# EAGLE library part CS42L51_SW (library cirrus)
CODEC (Software Mode) Low Power, Stereo CODEC with Headphone Amp
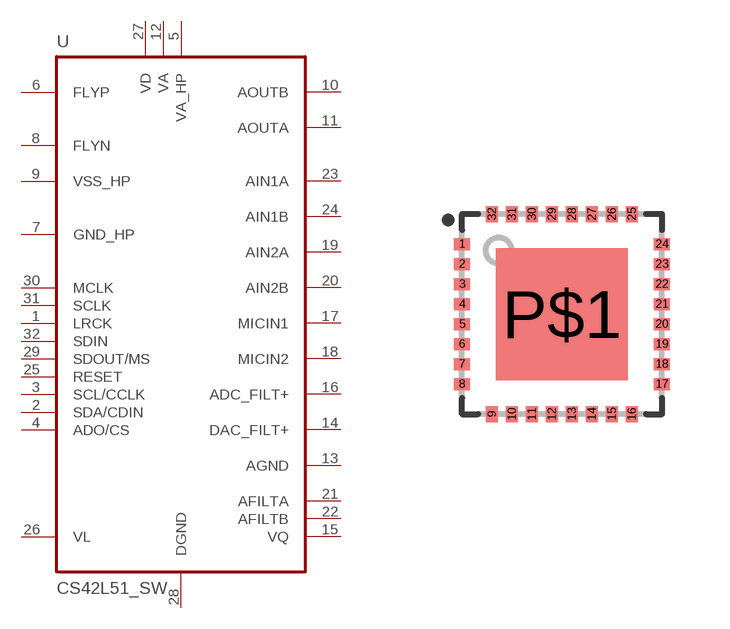
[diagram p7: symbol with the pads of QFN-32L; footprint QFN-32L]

Designator prefix U

## CS42L51_SW  [QFN-32L]
1  LRCK
2  SDA/CDIN
3  SCL/CCLK
4  ADO/CS
5  VA_HP
6  FLYP
7  GND_HP
8  FLYN
9  VSS_HP
10  AOUTB
11  AOUTA
12  VA
13  AGND
14  DAC_FILT+
15  VQ
16  ADC_FILT+
17  MICIN1
18  MICIN2
19  AIN2A
20  AIN2B
21  AFILTA
22  AFILTB
23  AIN1A
24  AIN1B
25  RESET
26  VL
27  VD
28  DGND
29  SDOUT/MS
30  MCLK
31  SCLK
32  SDIN

## Footprint QFN-32L (pad centres in mm)
QFN-32L body 5x5mm/JEDEC MO-220
smd 0.4 x 0.3: 1 -2.5,1.75; 2 -2.5,1.25; 3 -2.5,0.75; 4 -2.5,0.25; 5 -2.5,-0.25; 6 -2.5,-0.75; 7 -2.5,-1.25; 8 -2.5,-1.75; 17 2.5,-1.75; 18 2.5,-1.25; 19 2.5,-0.75; 20 2.5,-0.25; 21 2.5,0.25; 22 2.5,0.75; 23 2.5,1.25; 24 2.5,1.75
smd 0.3 x 0.4: 9 -1.75,-2.5; 10 -1.25,-2.5; 11 -0.75,-2.5; 12 -0.25,-2.5; 13 0.25,-2.5; 14 0.75,-2.5; 15 1.25,-2.5; 16 1.75,-2.5; 25 1.75,2.5; 26 1.25,2.5; 27 0.75,2.5; 28 0.25,2.5; 29 -0.25,2.5; 30 -0.75,2.5; 31 -1.25,2.5; 32 -1.75,2.5
smd 3.3 x 3.3: P$1 0,0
